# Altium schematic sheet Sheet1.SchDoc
size A; SheetNumber: 1; SheetTotal: 2
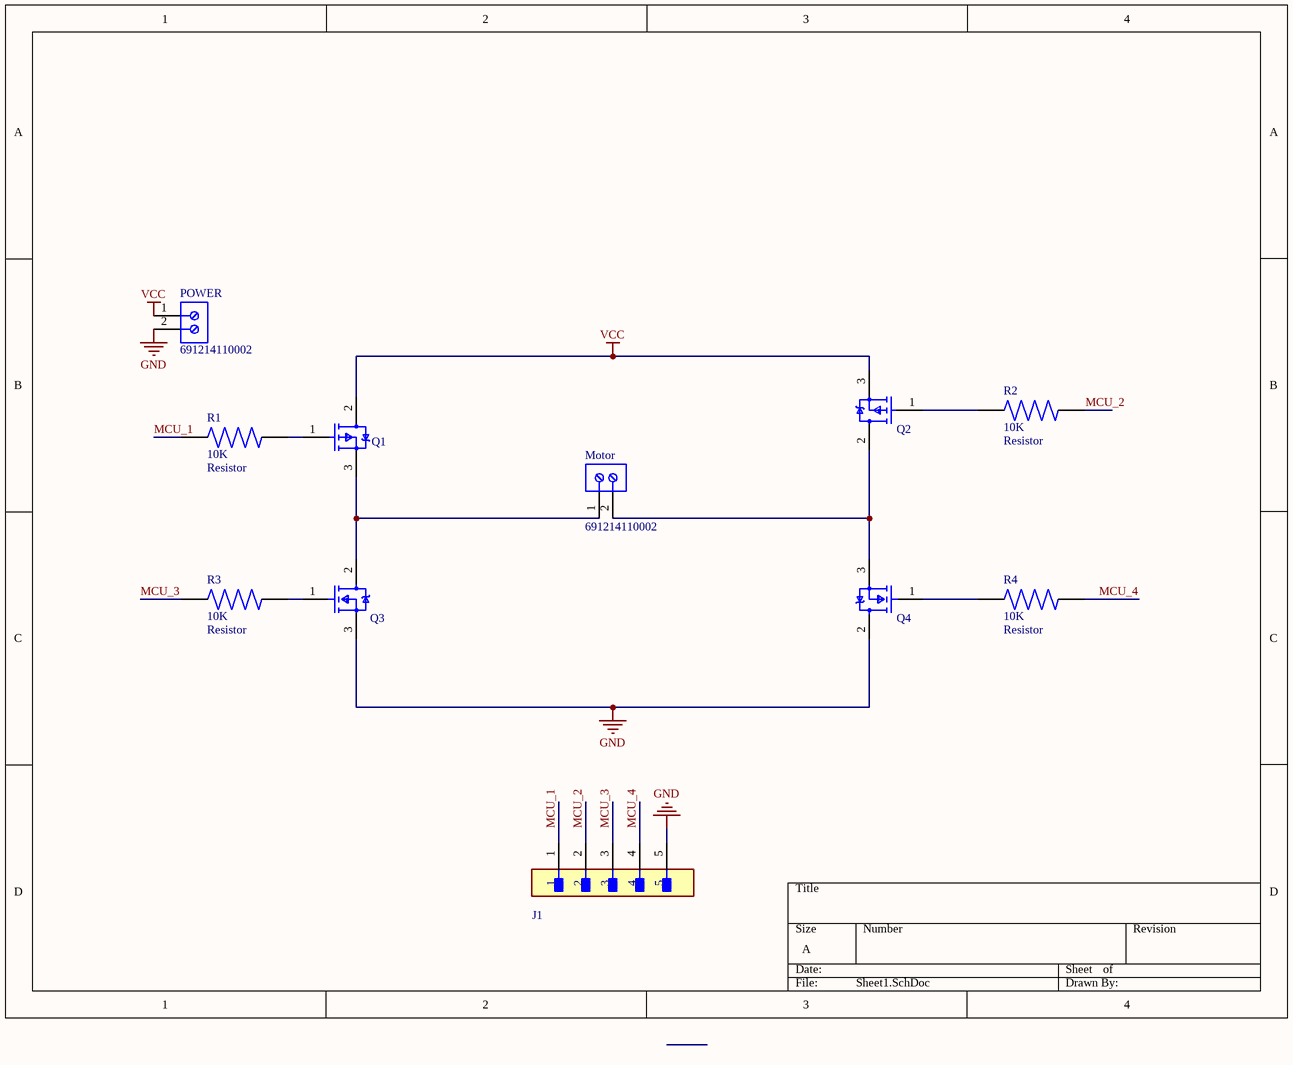
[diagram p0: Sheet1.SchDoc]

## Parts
J1  S5B-XH-A(LF)(SN)  [JST Conncetor 5 pins]  (value not drawn)
Motor  691214110002  [Terminal block]
POWER  691214110002  [Terminal block]
Q1  IRF4905PBF  [Mosfet P-Ch]  (value not drawn)
Q2  IRF4905PBF  [Mosfet P-Ch]  (value not drawn)
Q3  IRLZ44NPbF  [MOSFET N-CH 55V 47A TO220AB]  (value not drawn)
Q4  IRLZ44NPbF  [MOSFET N-CH 55V 47A TO220AB]  (value not drawn)
R1  Resistor  value 10K  [Resistor]
R2  Resistor  value 10K  [Resistor]
R3  Resistor  value 10K  [Resistor]
R4  Resistor  value 10K  [Resistor]

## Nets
GND: J1.5 POWER.2 Q3.3(S) Q4.2(D)
VCC: POWER.1 Q1.2(DRAIN) Q2.3(SOURCE)
MCU_1: J1.1 R1.1
MCU_2: J1.2 R2.2
MCU_3: J1.3 R3.1
MCU_4: J1.4 R4.2
NetMotor_1: Motor.1 Q1.3(SOURCE) Q3.2(D)
NetMotor_2: Motor.2 Q2.2(DRAIN) Q4.3(S)
NetQ1_1: Q1.1(GATE) R1.2
NetQ2_1: Q2.1(GATE) R2.1
NetQ3_1: Q3.1(G) R3.2
NetQ4_1: Q4.1(G) R4.1

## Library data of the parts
J1 = Jst conncetor 5 pins: CONN HEADER R/A 5POS 2.5MM; Contact Resistance: 10mR; Voltage Rating: 250V; Number of Contacts: 5; Current Rating: 3A; Insulation Resistance: 1GR; Wire/Cable Gauge: 22AWG
Motor POWER = Terminal block: NexarPartId: 18818288; Plating: Brass, Steel; Current: 10A; Pitch: 3.5052mm; Number of Levels: 1; Number of Contacts: 2; Wire Gauge (Min): 16AWG; Voltage: 300V; Wire Gauge (Max): 24AWG; Stripping Length: -6mm
Q1 Q2 = Mosfet P-CH: MOSFET P-CH 55V 74A TO-220AB; Drain to Source Resistance: 20mR; Input Capacitance: 3.4nF; Max Dual Supply Voltage: -55V; Power Dissipation: 200W; Turn-On Delay Time: 18ns; Element Configuration: Single; Threshold Voltage: -4V; Gate to Source Voltage (Vgs): 20V; Turn-Off Delay Time: 61ns
Q3 Q4 = MOSFET N-CH 55V 47A TO220AB: Continuous Drain Current (ID): 47A; Turn-On Delay Time: 11ns; Gate to Source Voltage (Vgs): 16V; Element Configuration: Single; Rds On Max: 22mR; Turn-Off Delay Time: 26ns; Max Power Dissipation: 110W; Threshold Voltage: 2V; Drain to Source Voltage (Vdss): 55V; Drain to Source Resistance: 35mR; Input Capacitance: 1.7nF
R1-R4 = Resistor: 10.2 kOhms Â±1% 0.25W, 1/4W Through Hole Resistor Axial - Metal Film; MF: Yageo; MP: MFR-25FBF52-10K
